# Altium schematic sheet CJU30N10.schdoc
size 127 x 101 mm
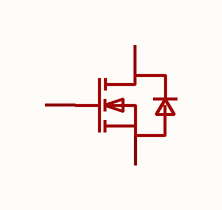
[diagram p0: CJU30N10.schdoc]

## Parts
Q?  cju30n10  [TO-252-2_L6.6-W6.1-P4.57-LS10.1-TL-CW]  (value not drawn)

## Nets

Not connected (* = marked no-connect by the designer): Q? 1(G) 2(D) 3(S)

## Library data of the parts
Q? = cju30n10: 数量:1个N沟道;漏源电压(Vdss):100V;连续漏极电流(Id):30A;导通电阻(RDS(on)):24mΩ@10V;耗散功率(Pd):85W;阈值电压(Vgs(th)):2.5V;; Manufacturer: CJ(江苏长电/长晶); AddInBom: yes; ModelId: 5d8ef1b124a64febb2ca91a0282fbfcc; ModelTransform: 397.637,259.842,0,0,0,0,38.819,0,0; Number: 1个N沟道; Drain to Source Voltage: 100V; Current - Continuous Drain(Id): 30A; Pd - Power Dissipation: 85W; Gate Threshold Voltage (Vgs(th)): 2.5V; Gate Charge(Qg): 124nC@10V; Input Capacitance(Ciss): 4.93nF; Reverse Transfer Capacitance (Crss@Vds): 216pF; Type: N沟道; Output Capacitance(Coss): 236pF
